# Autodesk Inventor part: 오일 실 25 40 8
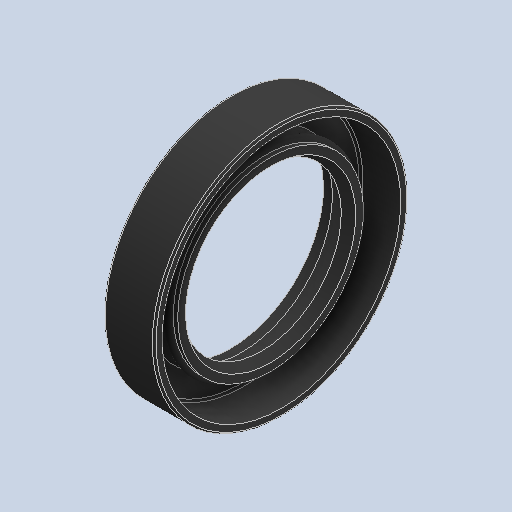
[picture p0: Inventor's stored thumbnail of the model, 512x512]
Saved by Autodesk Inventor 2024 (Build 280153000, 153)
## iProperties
Created: 2025-11
Part Number: 오일 실 25 40 8
Material: 고무
Description: 오일-실
Document SubType Name: Modeling
Designer: Edu07
Density: 0.93 g/cm^3
Appearance: 기본값
Author: jhkim
Sending System: Autodesk Inventor 2026
Preprocessor: ST-DEVELOPER v20.1
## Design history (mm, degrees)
node "오일 실 25 40 81"
node "솔리드1"
body "Solid1"
